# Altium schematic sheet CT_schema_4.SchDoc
size 207 x 169 mm
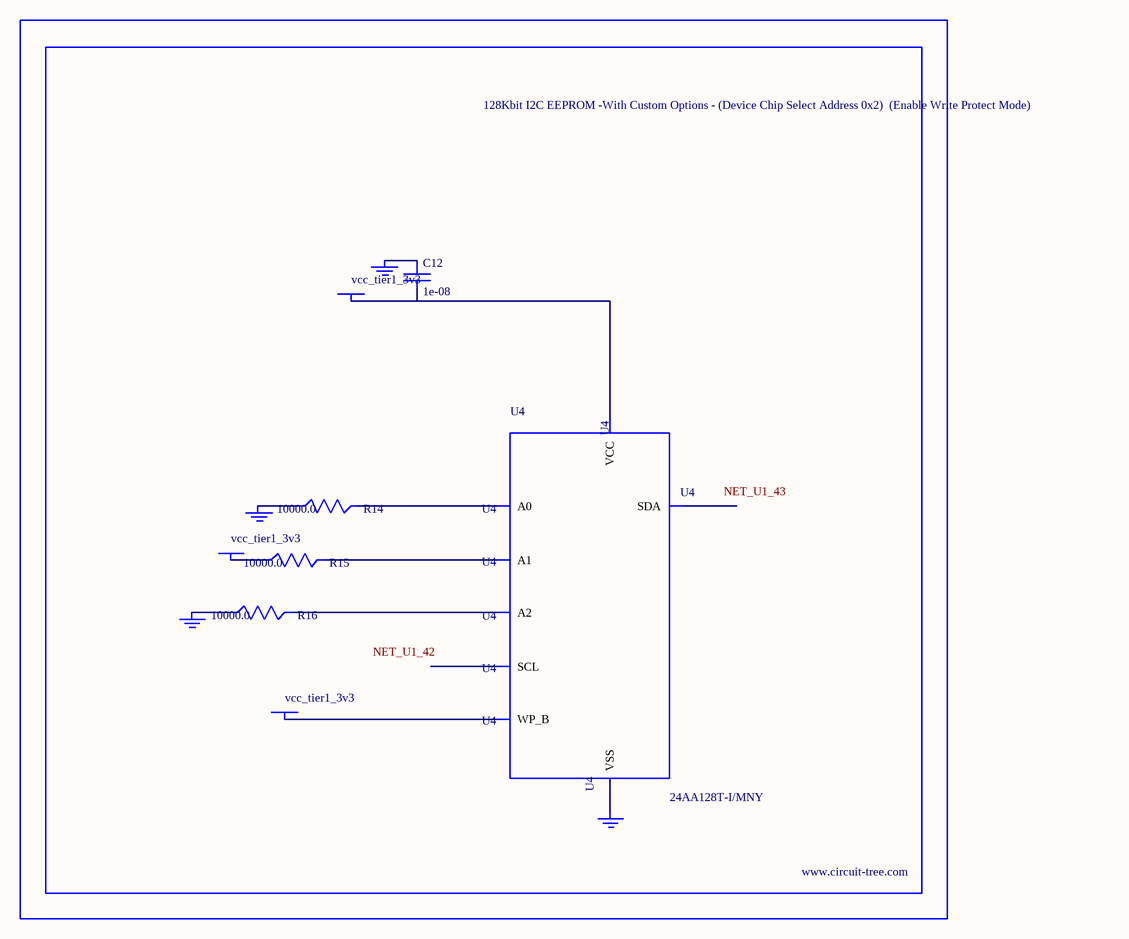
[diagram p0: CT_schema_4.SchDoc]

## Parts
BORDER3  (no value)
C12  1e-08  [C0402]
GND_INSTANCE_3_0  (no value)
GND_INSTANCE_3_1  (no value)
GND_INSTANCE_3_2  (no value)
GND_INSTANCE_3_3  (no value)
POWER_INSTANCE_3_0  vcc_tier1_3v3
POWER_INSTANCE_3_1  vcc_tier1_3v3
POWER_INSTANCE_3_2  vcc_tier1_3v3
R14  10000.0  [R0603]
R15  10000.0  [R0603]
R16  10000.0  [R0603]
U4  24AA128T-I/MNY  [TDFN-8/6MM]

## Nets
NetC12_1: C12.1 GND_INSTANCE_3_2.0(GND)
NetC12_2: C12.2 POWER_INSTANCE_3_2.0(PWR) U4.8(VCC)
NetGND_INSTANCE_3_0_0: GND_INSTANCE_3_0.0(GND) R14.1
NetGND_INSTANCE_3_1_0: GND_INSTANCE_3_1.0(GND) R16.1
NetGND_INSTANCE_3_3_0: GND_INSTANCE_3_3.0(GND) U4.4(VSS)
NetPOWER_INSTANCE_3_0_0: POWER_INSTANCE_3_0.0(PWR) R15.1
NetPOWER_INSTANCE_3_1_0: POWER_INSTANCE_3_1.0(PWR) U4.7(WP_B)
NetR14_2: R14.2 U4.1(A0)
NetR15_2: R15.2 U4.2(A1)
NetR16_2: R16.2 U4.3(A2)

Not connected (* = marked no-connect by the designer): U4 5(SDA) 6(SCL)

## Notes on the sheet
- Labels drawn without touching a wire or pin: NET_U1_42, NET_U1_43

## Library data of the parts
BORDER3 = BORDER_PAGE3
C12 = C0402C103K3RAC
GND_INSTANCE_3_0-GND_INSTANCE_3_3 = GND
POWER_INSTANCE_3_0-POWER_INSTANCE_3_2 = PWR
R14-R16 = RC0603JR-0710KL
